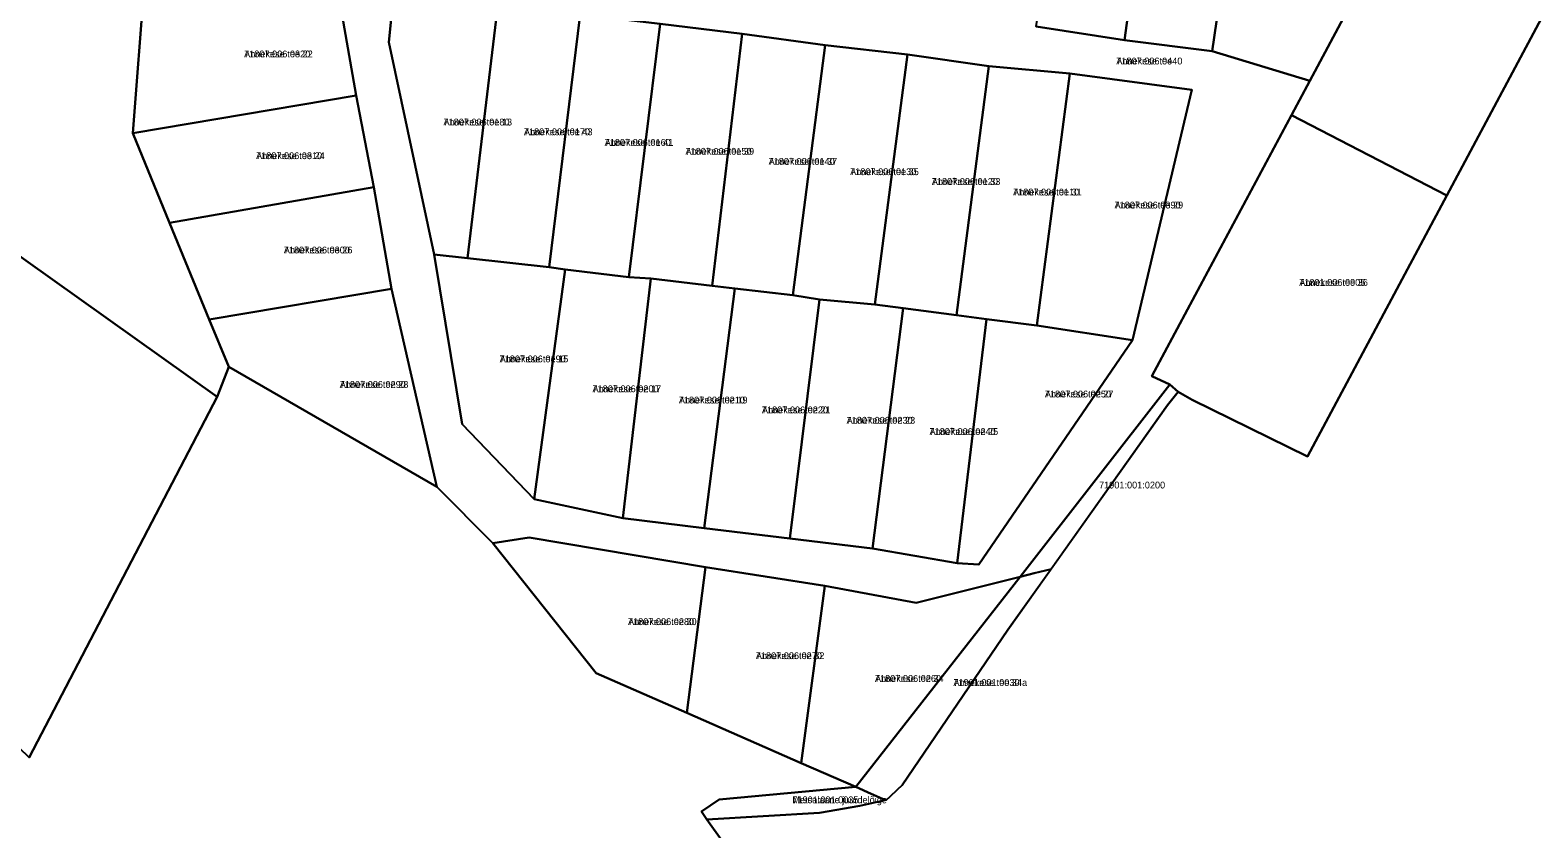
# Model space of a CAD drawing. Extents: x 529768 to 552006, y 6562269 to 6580975.
# Drawn here: x 537786.2 to 538116.9, y 6569289.3 to 6569464.5 of the extents above; entities that cross this region are included whole.
import ezdxf

# ---------------------------------------------------------------- set-up
doc = ezdxf.new("R2010")
doc.units = 0
for name, color, linetype in [('L_AADRESS', 7, 'Continuous'), ('PIIR', 7, 'Continuous'), ('TUNNUS', 7, 'Continuous')]:
    doc.layers.add(name, color=color, linetype=linetype)

msp = doc.modelspace()

# ---------------------------------------------------------------- linework, layer by layer
at = {"layer": 'PIIR'}
for points in [[(537644.87, 6569513.8), (537745.56, 6569682.43), (537776.26, 6569709.01), (537777.15, 6569706.14), (537791.22, 6569661.26), (537799.74, 6569628.48), (537806.35, 6569603.16), (537817.69, 6569559.7), (537816.3, 6569541.46), (537814.78, 6569521.51), (537813.21, 6569500.95), (537811.25, 6569475.13), (537808.72, 6569441.91), (537816.76, 6569422.27), (537825.47, 6569401.03), (537829.72, 6569390.65), (537827.2, 6569384.07), (537652.4, 6569508.66), (537646.93, 6569512.39)], [(538015.12, 6569516.15), (538033.21, 6569513.67), (538026.22, 6569462.3), (538006.8, 6569465.27)], [(538033.21, 6569513.67), (538052.88, 6569510.98), (538045.42, 6569459.88), (538026.22, 6569462.3)], [(537624.58, 6569461.25), (537652.4, 6569508.66), (537827.2, 6569384.07), (537785.99, 6569305), (537775.21, 6569315.27), (537640.51, 6569393.56), (537631.6, 6569403.29), (537627.83, 6569414.98), (537626.51, 6569454)], [(538045.42, 6569459.88), (538052.88, 6569510.98), (538094.58, 6569505.28), (538066.82, 6569453.38)], [(538094.58, 6569505.28), (538126.84, 6569484.47), (538096.86, 6569428.25), (538062.81, 6569445.87), (538066.82, 6569453.38)], [(537811.25, 6569475.13), (537854.32, 6569469.37), (537857.69, 6569450.14), (537808.72, 6569441.91)], [(537864.82, 6569461.87), (537866.03, 6569473.46), (537888.82, 6569470.57), (537882.09, 6569414.52), (537874.77, 6569415.32)], [(537888.82, 6569470.57), (537866.03, 6569473.46), (537864.82, 6569461.87), (537874.77, 6569415.32), (537880.93, 6569378.1), (537896.74, 6569361.67), (537916.15, 6569357.47), (537934.02, 6569355.27), (537952.81, 6569353.02), (537970.96, 6569350.8), (537989.52, 6569347.64), (537994.26, 6569347.32), (538027.94, 6569396.54), (538040.99, 6569451.4), (538014.18, 6569454.95), (537996.41, 6569456.59), (537978.62, 6569459.16), (537960.51, 6569461.22), (537942.31, 6569463.71), (537924.38, 6569465.87), (537906.84, 6569467.9)], [(537888.82, 6569470.57), (537906.84, 6569467.9), (537899.98, 6569412.55), (537882.09, 6569414.52)], [(537899.98, 6569412.55), (537906.84, 6569467.9), (537924.38, 6569465.87), (537917.49, 6569410.32), (537903.52, 6569411.99)], [(537917.49, 6569410.32), (537924.38, 6569465.87), (537942.31, 6569463.71), (537935.76, 6569408.45), (537922.27, 6569410.02)], [(537935.76, 6569408.45), (537942.31, 6569463.71), (537960.51, 6569461.22), (537953.44, 6569406.38), (537940.74, 6569407.87)], [(537953.44, 6569406.38), (537960.51, 6569461.22), (537978.62, 6569459.16), (537971.46, 6569404.33), (537959.31, 6569405.42)], [(537971.46, 6569404.33), (537978.62, 6569459.16), (537996.41, 6569456.59), (537989.32, 6569402), (537977.65, 6569403.52)], [(537989.32, 6569402), (537996.41, 6569456.59), (538014.18, 6569454.95), (538007, 6569399.69), (537995.9, 6569401.14)], [(538014.18, 6569454.95), (538040.99, 6569451.4), (538027.94, 6569396.54), (538007, 6569399.69)], [(537808.72, 6569441.91), (537857.69, 6569450.14), (537861.58, 6569430.03), (537816.76, 6569422.27)], [(538062.81, 6569445.87), (538096.86, 6569428.25), (538066.31, 6569370.97), (538041.07, 6569383.44), (538037.93, 6569385.18), (538036.17, 6569386.81), (538032.17, 6569388.58)], [(537816.76, 6569422.27), (537861.58, 6569430.03), (537865.43, 6569407.73), (537825.47, 6569401.03)], [(537896.74, 6569361.67), (537880.93, 6569378.1), (537874.77, 6569415.32), (537882.09, 6569414.52), (537899.98, 6569412.55), (537903.52, 6569411.99)], [(537903.52, 6569411.99), (537917.49, 6569410.32), (537922.27, 6569410.02), (537916.15, 6569357.47), (537896.74, 6569361.67)], [(537922.27, 6569410.02), (537935.76, 6569408.45), (537940.74, 6569407.87), (537934.02, 6569355.27), (537916.15, 6569357.47)], [(537875.39, 6569364.34), (537829.72, 6569390.65), (537825.47, 6569401.03), (537865.43, 6569407.73)], [(537940.74, 6569407.87), (537953.44, 6569406.38), (537959.31, 6569405.42), (537952.81, 6569353.02), (537934.02, 6569355.27)], [(537959.31, 6569405.42), (537971.46, 6569404.33), (537977.65, 6569403.52), (537970.96, 6569350.8), (537952.81, 6569353.02)], [(537977.65, 6569403.52), (537989.32, 6569402), (537995.9, 6569401.14), (537989.52, 6569347.64), (537970.96, 6569350.8)], [(537989.52, 6569347.64), (537995.9, 6569401.14), (538007, 6569399.69), (538027.94, 6569396.54), (537994.26, 6569347.32)], [(538010.08, 6569346.32), (538006.36, 6569345.39), (538005.26, 6569345.11), (538003.3, 6569344.62), (538036.17, 6569386.81), (538037.93, 6569385.18), (538035.62, 6569382.26)], [(537910.34, 6569323.52), (537887.64, 6569351.98), (537895.6, 6569353.26), (537934.26, 6569346.75), (537930.2, 6569314.79)], [(537955.26, 6569303.77), (537930.2, 6569314.79), (537934.26, 6569346.75), (537960.46, 6569342.63)], [(537967.26, 6569298.54), (538003.28, 6569344.6), (538006.36, 6569345.39), (538010.08, 6569346.32), (538000.62, 6569333.01), (537977.46, 6569298.96), (537976.43, 6569298), (537974.72, 6569296.39), (537973.98, 6569295.7), (537973.75, 6569295.65), (537970.65, 6569297.02)], [(537980.48, 6569338.91), (538003.28, 6569344.6), (537967.26, 6569298.54), (537955.26, 6569303.77), (537960.46, 6569342.63)], [(537934.56, 6569291.38), (537933.41, 6569293.13), (537937.3, 6569295.77), (537967.26, 6569298.54), (537970.65, 6569297.02), (537973.75, 6569295.65), (537968.17, 6569294.43), (537959.31, 6569292.88)]]:
    msp.add_lwpolyline(points, close=True, dxfattribs=at)
for points in [[(538082.64, 6569084.58), (538063.49, 6569111.53), (537934.56, 6569291.38), (537959.31, 6569292.88), (537968.17, 6569294.43), (537973.98, 6569295.7), (537974.72, 6569296.39), (537976.43, 6569298), (537977.46, 6569298.96), (538000.62, 6569333.01), (538035.62, 6569382.26), (538037.93, 6569385.18), (538041.07, 6569383.44), (538066.31, 6569370.97), (538096.86, 6569428.25), (538126.84, 6569484.47), (538094.58, 6569505.28), (538097.36, 6569520.89), (538101.52, 6569544.2), (538104.87, 6569562.99), (538108.45, 6569583.07), (538112.25, 6569604.38), (538112.71, 6569609.04), (538119.76, 6569607.91)], [(538006.8, 6569465.27), (538026.22, 6569462.3), (538045.42, 6569459.88), (538066.82, 6569453.38), (538032.17, 6569388.58), (538036.17, 6569386.81), (538003.28, 6569344.6), (537980.48, 6569338.91), (537960.46, 6569342.63), (537934.26, 6569346.75), (537895.6, 6569353.26), (537887.64, 6569351.98), (537875.39, 6569364.34), (537865.43, 6569407.73), (537861.58, 6569430.03), (537857.69, 6569450.14), (537854.32, 6569469.37)], [(537721.35, 6569289.12), (537573.72, 6569375.48), (537624.58, 6569461.25), (537626.51, 6569454), (537627.83, 6569414.98), (537631.6, 6569403.29), (537640.51, 6569393.56), (537775.21, 6569315.27), (537785.99, 6569305), (537827.2, 6569384.07), (537829.72, 6569390.65), (537875.39, 6569364.34), (537887.64, 6569351.98), (537910.34, 6569323.52), (537930.2, 6569314.79), (537955.26, 6569303.77), (537967.26, 6569298.54), (537937.3, 6569295.77), (537933.41, 6569293.13), (537934.56, 6569291.38), (538063.49, 6569111.53)]]:
    msp.add_lwpolyline(points, dxfattribs=at)

# ---------------------------------------------------------------- texts
at = {"layer": 'L_AADRESS'}
for s, p in [('Annekese tee 22', (537833.1, 6569458.52)), ('Annekese tee', (538024.39, 6569456.97)), ('Annekese tee 13', (537876.82, 6569443.59)), ('Annekese tee 43', (537894.47, 6569441.45)), ('Annekese tee 41', (537912.18, 6569439.12)), ('Annekese tee 39', (537929.9, 6569437.17)), ('Annekese tee 24', (537835.72, 6569436.21)), ('Annekese tee 37', (537948.13, 6569434.96)), ('Annekese tee 35', (537966.03, 6569432.7)), ('Annekese tee 33', (537983.93, 6569430.55)), ('Annekese tee 31', (538001.75, 6569428.24)), ('Annekese tee 29', (538024, 6569425.39)), ('Annekese tee 26', (537841.8, 6569415.53)), ('Annekese tee 36', (538064.52, 6569408.42)), ('Annekese tee 15', (537889.15, 6569391.65)), ('Annekese tee 28', (537854.07, 6569386.04)), ('Annekese tee 17', (537909.51, 6569385.09)), ('Annekese tee 27', (538008.73, 6569383.95)), ('Annekese tee 19', (537928.45, 6569382.63)), ('Annekese tee 21', (537946.67, 6569380.47)), ('Annekese tee 23', (537965.23, 6569378.19)), ('Annekese tee 25', (537983.43, 6569375.72)), ('Annekese tee 30', (537917.3, 6569334.03)), ('Annekese tee 32', (537945.33, 6569326.57)), ('Annekese tee 34', (537971.46, 6569321.57)), ('Annekese tee 34a', (537988.67, 6569320.68)), ('Metsalaane juurdelõige', (537953.35, 6569294.96))]:
    msp.add_text(s, height=1.5, dxfattribs=at).set_placement(p)
at = {"layer": 'TUNNUS'}
for s, p in [('71807:006:0320', (537833.1, 6569458.52)), ('71807:006:0440', (538024.39, 6569456.97)), ('71807:006:0180', (537876.82, 6569443.59)), ('71807:006:0170', (537894.47, 6569441.45)), ('71807:006:0160', (537912.18, 6569439.12)), ('71807:006:0150', (537929.9, 6569437.17)), ('71807:006:0310', (537835.72, 6569436.21)), ('71807:006:0140', (537948.13, 6569434.96)), ('71807:006:0130', (537966.03, 6569432.7)), ('71807:006:0120', (537983.93, 6569430.55)), ('71807:006:0110', (538001.75, 6569428.24)), ('71807:006:0390', (538024, 6569425.39)), ('71807:006:0300', (537841.8, 6569415.53)), ('71801:006:0905', (538064.52, 6569408.42)), ('71807:006:0190', (537889.15, 6569391.65)), ('71807:006:0290', (537854.07, 6569386.04)), ('71807:006:0200', (537909.51, 6569385.09)), ('71807:006:0250', (538008.73, 6569383.95)), ('71807:006:0210', (537928.45, 6569382.63)), ('71807:006:0220', (537946.67, 6569380.47)), ('71807:006:0230', (537965.23, 6569378.19)), ('71807:006:0240', (537983.43, 6569375.72)), ('71901:001:0200', (538020.61, 6569363.99)), ('71807:006:0280', (537917.3, 6569334.03)), ('71807:006:0270', (537945.33, 6569326.57)), ('71807:006:0260', (537971.46, 6569321.57)), ('71901:001:0030', (537988.67, 6569320.68)), ('71901:001:0035', (537953.35, 6569294.96))]:
    msp.add_text(s, height=1.5, dxfattribs=at).set_placement(p)

doc.saveas('drawing.dxf')
